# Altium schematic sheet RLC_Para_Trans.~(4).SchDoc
size A4
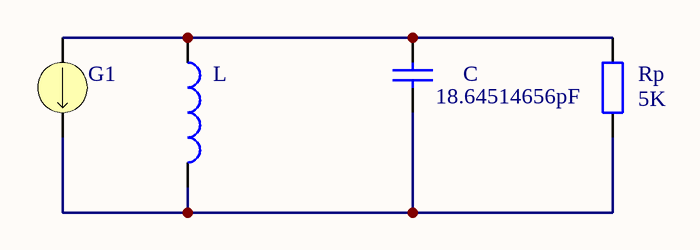
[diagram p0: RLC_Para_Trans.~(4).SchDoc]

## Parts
C  value 18.64514656pF  [RAD-0.3]  (hidden comment: Cap)
G1  ISRC  (value not drawn)
L  Inductor  [0402-A]  (value not drawn)
Rp  value 5K  [AXIAL-0.4]  (hidden comment: Res2)

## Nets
NetC_1: C.1 G1.2 L.2 Rp.1
NetC_2: C.2 G1.1 L.1 Rp.2

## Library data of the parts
C = Cap: Capacitor
G1 = ISRC: Current Source; Note: PCB Footprint - Not required; Value: 1mA
L = Inductor: Code_IEC: 1005
Rp = Res2: Resistor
